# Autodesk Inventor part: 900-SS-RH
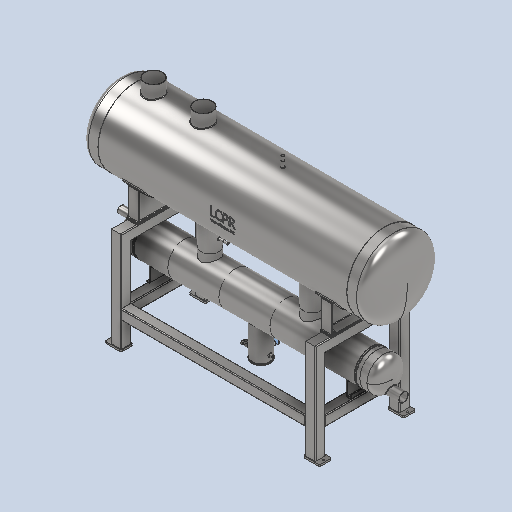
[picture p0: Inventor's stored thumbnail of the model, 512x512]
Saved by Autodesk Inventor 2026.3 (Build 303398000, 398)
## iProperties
Created: 2026-05
Part Number: 900-SS-RH
Material: Generic
Document SubType Name: Modeling
Designer: rva
Density: 1 g/cm^3
Appearance: Default
Author: rva
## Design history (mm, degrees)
derived "LCPR-SS-900-RH.iam"
body "Solid1"
node "Sub-SS-400-200-2646-200-100-75-RH.iam:1::LCPR-SS-400 mm Subc"
node "Sub-SS-400-200-2646-200-100-75-RH.iam:1::LCPR-SS-400 mm Subc"
node "Sub-SS-400-200-2646-200-100-75-RH.iam:1::H1100-R.ipt:2"
node "Sub-SS-400-200-2646-200-100-75-RH.iam:1::1-2 Inch NPT Socket"
node "Sub-SS-400-200-2646-200-100-75-RH.iam:1::Welds"
node "LPR-900-Frame Assembly.iam:1::LCPR-SS-Frame FOOT PLATE 195 x"
node "LPR-900-Frame Assembly.iam:1::LCPR-SS-Frame FOOT PLATE 195 x"
node "LPR-900-Frame Assembly.iam:1::LCPR-SS-Frame FOOT PLATE 195 x"
node "LPR-900-Frame Assembly.iam:1::LCPR-SS-Frame FOOT PLATE 195 x"
node "Nylon Heat Tranfer Spacer 760x125.ipt:1"
node "Nylon Heat Tranfer Spacer 760x125.ipt:2"
node "AS 1111 - Metric M16 x 160:1"
node "AS 1112 (4) - Metric M16:1"
node "AS 1237 (4.2) 16 mm:1"
node "AS 1237 (4.2) 16 mm:2"
node "AS 1111 - Metric M16 x 160:2"
node "AS 1112 (4) - Metric M16:2"
node "AS 1237 (4.2) 16 mm:3"
node "AS 1237 (4.2) 16 mm:4"
node "AS 1111 - Metric M16 x 160:3"
node "AS 1112 (4) - Metric M16:3"
node "AS 1237 (4.2) 16 mm:5"
node "AS 1237 (4.2) 16 mm:6"
node "AS 1111 - Metric M16 x 160:4"
node "AS 1112 (4) - Metric M16:4"
node "AS 1237 (4.2) 16 mm:7"
node "AS 1237 (4.2) 16 mm:8"
node "LCPR-SS-900-3000-200-WELD.iam:1::900 mm LOGO.iam:1::LCPR-LOG"
node "LCPR-SS-900-3000-200-WELD.iam:1::H1100-R.ipt:1"
node "LCPR-SS-900-3000-200-WELD.iam:1::LCPR-SS-900-Leg Assembly.ia"
node "LCPR-SS-900-3000-200-WELD.iam:1::900 mm-SS-Dome End Cap.ipt:"
node "LCPR-SS-900-3000-200-WELD.iam:1::LCPR-SS-900-Leg Assembly.ia"
node "LCPR-SS-900-3000-200-WELD.iam:1::900 mm-SS-Dome End Cap.ipt:"
node "LCPR-SS-900-3000-200-WELD.iam:1::Welds"
node "LCPR-SS-900-RH.iam_Bodies"
